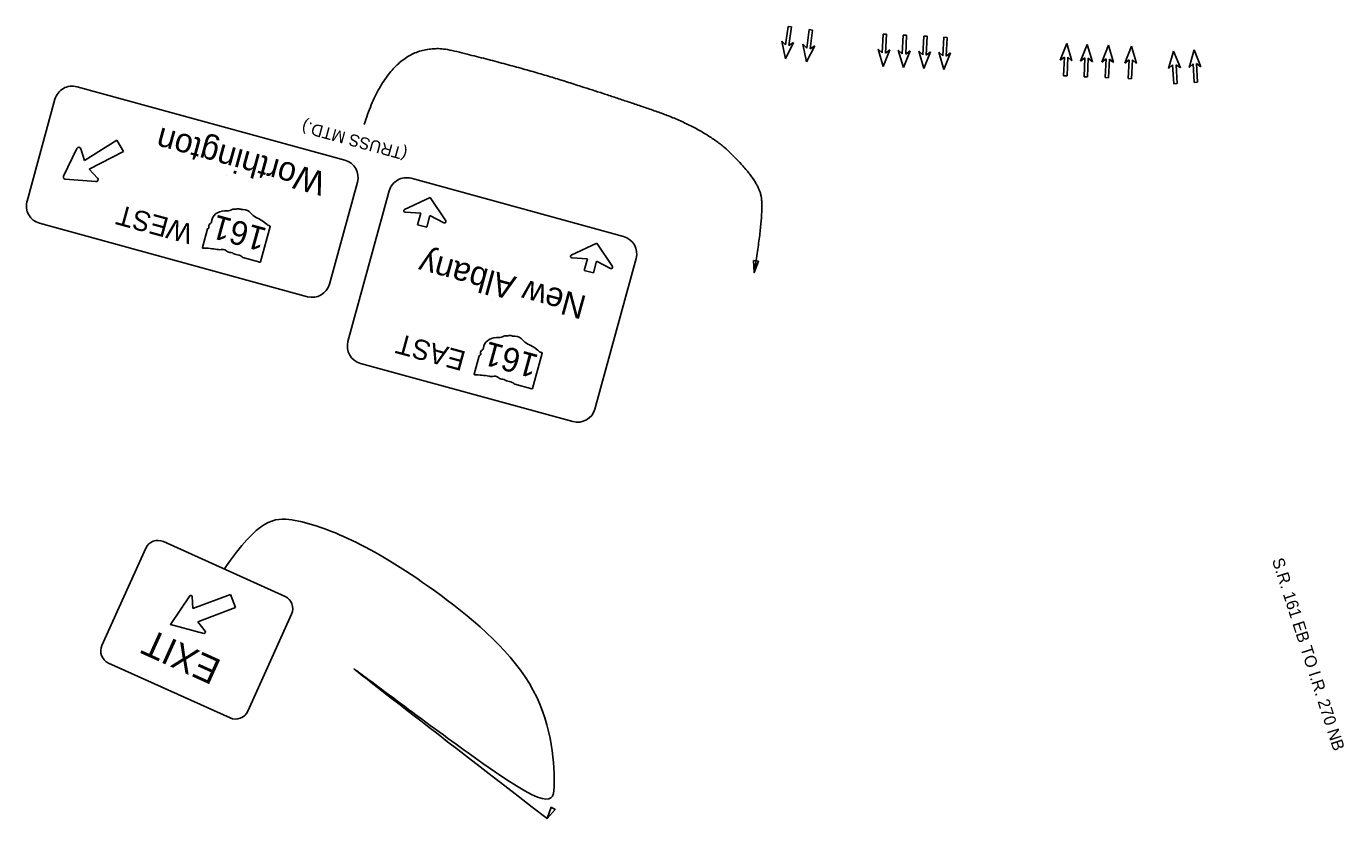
# Model space of a CAD drawing. Extents: x 217413 to 218294, y 612415 to 614235.
# Drawn here: x 217522 to 218294, y 613771 to 614235 of the extents above; entities that cross this region are included whole.
import ezdxf

# ---------------------------------------------------------------- set-up
doc = ezdxf.new("R2010")
doc.units = 0
for name, color, linetype in [('MT_P_Cells', 7, 'Continuous'), ('SH_Text', 7, 'Continuous'), ('SN_P_Text', 7, 'Continuous'), ('SN_X_Public', 7, 'Continuous')]:
    doc.layers.add(name, color=color, linetype=linetype)

msp = doc.modelspace()

# ---------------------------------------------------------------- linework, layer by layer
at = {"layer": 'MT_P_Cells'}
for p, q in [((217966.86, 614223.97), (217968.31, 614234.88)), ((217968.31, 614234.88), (217970.29, 614234.61)), ((217970.29, 614234.61), (217968.84, 614223.71)), ((217969.3, 614234.74), (217969.3, 614234.74)), ((217979.21, 614222.06), (217980.66, 614232.97)), ((217980.66, 614232.97), (217982.64, 614232.7)), ((217982.64, 614232.7), (217981.2, 614221.8)), ((217981.65, 614232.84), (217981.65, 614232.84)), ((218023.39, 614219.35), (218023.93, 614230.34)), ((218023.93, 614230.34), (218025.93, 614230.24)), ((218024.93, 614230.29), (218024.93, 614230.29)), ((218025.93, 614230.24), (218025.38, 614219.25)), ((218035.24, 614218.76), (218035.79, 614229.74)), ((218035.79, 614229.74), (218037.78, 614229.64)), ((218036.78, 614229.69), (218036.78, 614229.69)), ((218037.78, 614229.64), (218037.24, 614218.66)), ((218047.27, 614218.15), (218047.81, 614229.13)), ((218047.81, 614229.13), (218049.81, 614229.04)), ((218048.81, 614229.08), (218048.81, 614229.08)), ((218049.81, 614229.04), (218049.27, 614218.05)), ((218058.95, 614217.55), (218059.49, 614228.54)), ((218059.49, 614228.54), (218061.49, 614228.44)), ((218060.49, 614228.49), (218060.49, 614228.49)), ((218061.49, 614228.44), (218060.95, 614217.46)), ((217966.8, 614215.91), (217964.67, 614226.28)), ((217964.67, 614226.28), (217966.86, 614223.97)), ((217971.56, 614225.37), (217966.8, 614215.91)), ((217968.84, 614223.71), (217971.56, 614225.37)), ((217979.15, 614214), (217977.03, 614224.37)), ((217977.03, 614224.37), (217979.21, 614222.06)), ((217983.91, 614223.46), (217979.15, 614214)), ((217981.2, 614221.8), (217983.91, 614223.46)), ((218023.99, 614211.31), (218021.02, 614221.47)), ((218021.02, 614221.47), (218023.39, 614219.35)), ((218027.95, 614221.13), (218023.99, 614211.31)), ((218025.38, 614219.25), (218027.95, 614221.13)), ((218035.85, 614210.72), (218032.87, 614220.87)), ((218032.87, 614220.87), (218035.24, 614218.76)), ((218039.81, 614220.53), (218035.85, 614210.72)), ((218037.24, 614218.66), (218039.81, 614220.53)), ((218047.87, 614210.11), (218044.9, 614220.27)), ((218044.9, 614220.27), (218047.27, 614218.15)), ((218051.83, 614219.92), (218047.87, 614210.11)), ((218049.27, 614218.05), (218051.83, 614219.92)), ((218059.55, 614209.52), (218056.58, 614219.67)), ((218056.58, 614219.67), (218058.95, 614217.55)), ((218063.51, 614219.33), (218059.55, 614209.52)), ((218060.95, 614217.46), (218063.51, 614219.33)), ((218127.64, 614215.02), (218131.55, 614224.86)), ((218131.55, 614224.86), (218131.55, 614224.86)), ((218131.55, 614224.86), (218134.58, 614214.71)), ((218139.61, 614214.47), (218143.53, 614224.31)), ((218143.53, 614224.31), (218143.53, 614224.31)), ((218143.53, 614224.31), (218146.55, 614214.17)), ((218152.02, 614213.93), (218155.93, 614223.77)), ((218155.93, 614223.77), (218155.93, 614223.77)), ((218155.93, 614223.77), (218158.95, 614213.62)), ((218165.5, 614213.37), (218169.41, 614223.2)), ((218169.41, 614223.2), (218169.41, 614223.2)), ((218169.41, 614223.2), (218172.43, 614213.06)), ((218191.23, 614210.12), (218194.12, 614220.31)), ((218194.12, 614220.31), (218194.12, 614220.31)), ((218194.12, 614220.31), (218198.16, 614210.52)), ((218203.24, 614210.85), (218206.13, 614221.03)), ((218206.13, 614221.03), (218206.13, 614221.03)), ((218206.13, 614221.03), (218210.17, 614211.25)), ((217966.8, 614215.91), (217966.8, 614215.91)), ((217979.15, 614214), (217979.15, 614214)), ((218023.99, 614211.31), (218023.99, 614211.31)), ((218130.2, 614216.91), (218127.64, 614215.02)), ((218129.71, 614205.92), (218130.2, 614216.91)), ((218132.2, 614216.82), (218131.71, 614205.83)), ((218134.58, 614214.71), (218132.2, 614216.82)), ((218142.17, 614216.36), (218139.61, 614214.47)), ((218141.68, 614205.37), (218142.17, 614216.36)), ((218144.17, 614216.27), (218143.68, 614205.28)), ((218146.55, 614214.17), (218144.17, 614216.27)), ((218154.57, 614215.82), (218152.02, 614213.93)), ((218154.09, 614204.83), (218154.57, 614215.82)), ((218156.57, 614215.73), (218156.08, 614204.74)), ((218158.95, 614213.62), (218156.57, 614215.73)), ((218168.06, 614215.26), (218165.5, 614213.37)), ((218167.57, 614204.27), (218168.06, 614215.26)), ((218170.05, 614215.17), (218169.57, 614204.18)), ((218172.43, 614213.06), (218170.05, 614215.17)), ((218193.58, 614212.26), (218191.23, 614210.12)), ((218194.22, 614201.28), (218193.58, 614212.26)), ((218198.16, 614210.52), (218195.58, 614212.38)), ((218195.58, 614212.38), (218196.22, 614201.4)), ((218205.59, 614212.99), (218203.24, 614210.85)), ((218206.23, 614202.01), (218205.59, 614212.99)), ((218210.17, 614211.25), (218207.59, 614213.1)), ((218207.59, 614213.1), (218208.22, 614202.12)), ((218035.85, 614210.72), (218035.85, 614210.72)), ((218047.87, 614210.11), (218047.87, 614210.11)), ((218059.55, 614209.52), (218059.55, 614209.52)), ((218131.71, 614205.83), (218129.71, 614205.92)), ((218130.71, 614205.88), (218130.71, 614205.88)), ((218143.68, 614205.28), (218141.68, 614205.37)), ((218142.68, 614205.33), (218142.68, 614205.33)), ((218156.08, 614204.74), (218154.09, 614204.83)), ((218155.08, 614204.78), (218155.08, 614204.78)), ((218169.57, 614204.18), (218167.57, 614204.27)), ((218168.57, 614204.22), (218168.57, 614204.22)), ((218196.22, 614201.4), (218194.22, 614201.28)), ((218195.22, 614201.34), (218195.22, 614201.34)), ((218208.22, 614202.12), (218206.23, 614202.01)), ((218207.23, 614202.06), (218207.23, 614202.06))]:
    msp.add_line(p, q, dxfattribs=at)
at = {"layer": 'SH_Text'}
for points in [[(217948.15, 614097.71), (217950.91, 614097.25), (217948.38, 614090.57)], [(217829.48, 613777.32), (217831.89, 613775.91), (217827.15, 613770.57)]]:
    msp.add_lwpolyline(points, close=True, dxfattribs=at)
for points, degree in [([(217948.38, 614090.57), (217954.64, 614127.11), (217950.04, 614145.51), (217919.75, 614175.19), (217860.42, 614195.59), (217808.4, 614211.75), (217736.45, 614229.27), (217719.98, 614177.39)], 2), ([(217638.02, 613916.85), (217658.24, 613946.4), (217676.59, 613947.98), (217710.8, 613936.14), (217757.4, 613909.03), (217827.54, 613851.77), (217833.39, 613781.96), (217827.15, 613770.57), (217638.02, 613916.85), (217827.15, 613770.57)], 3)]:
    msp.add_open_spline(points, degree=degree, dxfattribs=at)
at = {"layer": 'SN_X_Public'}
for p, q in [((217551.79, 614199.49), (217708.66, 614156.49)), ((217522.47, 614132.42), (217538.83, 614192.11)), ((217556.1, 614156.23), (217575.19, 614168.19)), ((217575.19, 614168.19), (217578.95, 614161.58)), ((217543.87, 614147.12), (217551.72, 614163.34)), ((217554.02, 614163.16), (217556.1, 614156.23)), ((217578.95, 614161.58), (217558.93, 614151.26)), ((217558.93, 614151.26), (217563.83, 614145.94)), ((217562.82, 614143.87), (217544.86, 614145.38)), ((217639.43, 614147.74), (217639.43, 614147.74)), ((217716.05, 614143.53), (217699.68, 614083.84)), ((217747.61, 614145.82), (217871.93, 614111.74)), ((217758.57, 614134.66), (217743.63, 614127.46)), ((217767.74, 614120.85), (217758.57, 614134.66)), ((217686.72, 614076.46), (217529.85, 614119.46)), ((217744.03, 614125.95), (217753.16, 614125.47)), ((217753.16, 614125.47), (217751.28, 614118.59)), ((217751.28, 614118.59), (217756.64, 614117.12)), ((217756.64, 614117.12), (217758.53, 614124)), ((217758.53, 614124), (217766.63, 614119.76)), ((217625.19, 614105.35), (217628.15, 614116.12)), ((217664.98, 614117.51), (217659.34, 614096.92)), ((217856.21, 614107.89), (217841.28, 614100.69)), ((217865.39, 614094.08), (217856.21, 614107.89)), ((217658.9, 614096.66), (217648.98, 614099.38)), ((217841.68, 614099.18), (217850.81, 614098.7)), ((217850.81, 614098.7), (217848.93, 614091.83)), ((217854.29, 614090.36), (217856.18, 614097.23)), ((217856.18, 614097.23), (217864.28, 614092.99)), ((217848.93, 614091.83), (217854.29, 614090.36)), ((217794.9, 614074.53), (217794.9, 614074.53)), ((217784.42, 614031.11), (217787.37, 614041.88)), ((217824.2, 614043.26), (217818.56, 614022.68)), ((217842.19, 614003.24), (217717.87, 614037.32)), ((217818.13, 614022.41), (217808.2, 614025.14)), ((217619.19, 613900.66), (217619.2, 613900.66)), ((217619.2, 613900.66), (217619.61, 613893.69)), ((217619.61, 613893.69), (217641.66, 613902.01)), ((217641.66, 613902.01), (217644.6, 613894.21)), ((217644.6, 613894.21), (217622.56, 613885.89)), ((217626.03, 613879.14), (217606.47, 613884.28)), ((217622.56, 613885.89), (217626.84, 613880.38))]:
    msp.add_line(p, q, dxfattribs=at)
for points in [[(217710.49, 614050.28), (217734.65, 614138.43)], [(217879.31, 614098.78), (217855.15, 614010.62)], [(217566.34, 613872.09), (217592.09, 613929.04)], [(217602.42, 613932.94), (217673.61, 613900.75)], [(217606.47, 613884.28), (217606.47, 613884.28), (217617.76, 613901.05)], [(217677.51, 613890.42), (217651.76, 613833.47)], [(217641.42, 613829.57), (217570.24, 613861.75)]]:
    msp.add_lwpolyline(points, dxfattribs=at)
for centre, radius, start, end in [((217549.01, 614189.32), 10.55, 74.6708, 164.6708), ((217552.83, 614162.8), 1.24, 16.69459, 154.16791), ((217705.87, 614146.32), 10.55, 344.6708, 74.6708), ((217545, 614146.61), 1.24, 155.57716, 263.76444), ((217562.92, 614145.1), 1.24, 265.17369, 42.64701), ((217744.82, 614135.64), 10.55, 74.6708, 164.6708), ((217532.64, 614129.63), 10.55, 164.6708, 254.6708), ((217869.14, 614101.57), 10.55, 344.6708, 74.6708), ((217689.51, 614086.63), 10.55, 254.6708, 344.6708), ((217720.66, 614047.49), 10.55, 164.6708, 254.6708), ((217844.98, 614013.41), 10.55, 254.6708, 344.6708), ((217599.2, 613925.82), 7.81, 65.67027, 155.67027), ((217618.41, 613900.62), 0.781, 3.48975, 146.06263), ((217670.39, 613893.63), 7.81, 335.67027, 65.67027), ((217626.22, 613879.91), 0.781, 255.27791, 37.85079), ((217573.45, 613868.87), 7.81, 155.67027, 245.67027), ((217644.64, 613836.68), 7.81, 245.67027, 335.67027)]:
    msp.add_arc(centre, radius, start, end, dxfattribs=at)
for centre, major_axis, ratio, start_param, end_param in [((217639.82, 614119.24), (-8.99, 2.47), 0.8, 5.101752, 6.440018), ((217638.93, 614130.86), (-4.93, 1.35), 0.8, 1.647645, 2.488434), ((217644.13, 614125.37), (-2.91, 0.8), 0.8, 4.937069, 5.64225), ((217644.58, 614128.29), (-0.773, 0.212), 0.8, 1.147584, 2.315152), ((217646.52, 614125.62), (-2.75, 0.75), 0.8, 4.691044, 5.507374), ((217648.42, 614131.09), (-4.24, 1.16), 0.8, 1.495662, 1.94098), ((217649.45, 614123.15), (-5.16, 1.41), 0.8, 4.026481, 4.996735), ((217744.04, 614126.75), (0.825, -0.226), 0.925816, 2.325901, 4.943538), ((217632.54, 614117.23), (-3.51, 0.96), 0.8, 5.934695, 6.695948), ((217628.03, 614121), (-2.55, 0.7), 0.8, 2.387724, 3.262537), ((217660.42, 614128.7), (-8.12, 2.23), 0.8, 0.823519, 1.323587), ((217645.4, 614104.27), (-25.97, 7.12), 0.8, 4.195997, 4.488961), ((217664.23, 614118.99), (-1.09, 0.3), 0.8, 0.519207, 1.627899), ((217767.03, 614120.45), (-0.825, 0.226), 0.925815, 1.339647, 3.957285), ((217628.56, 614116.05), (-0.404, 0.111), 0.8, 5.05454, 6.418171), ((217628.45, 614116.89), (-0.584, 0.16), 0.8, 1.883978, 3.671073), ((217663.96, 614115.57), (-3.02, 0.83), 0.8, 4.665946, 4.897461), ((217664.6, 614117.66), (-0.396, 0.109), 0.8, 3.00124, 4.508301), ((217625.56, 614105.21), (-0.377, 0.103), 0.8, 6.141152, 7.989035), ((217629.72, 614074.49), (-35.96, 9.86), 0.8, 4.814394, 5.042369), ((217634.55, 614110.1), (-7.23, 1.98), 0.8, 1.699011, 2.107814), ((217637.49, 614101.8), (-2.75, 0.75), 0.8, 4.081561, 5.145723), ((217641.34, 614104.25), (-2.29, 0.63), 0.8, 0.950623, 2.079405), ((217642.3, 614101.43), (-1.1, 0.3), 0.8, 3.836095, 5.185415), ((217648.52, 614111.93), (-13.68, 3.75), 0.8, 1.404758, 1.657858), ((217645.96, 614097.64), (-3.81, 1.04), 0.8, 4.042523, 4.731795), ((217658.94, 614096.99), (-0.393, 0.108), 0.8, 1.712693, 3.28349), ((217841.69, 614099.98), (0.825, -0.226), 0.925816, 2.325901, 4.943538), ((217864.67, 614093.68), (-0.825, 0.226), 0.925815, 1.339647, 3.957285), ((217799.04, 614044.99), (-8.99, 2.47), 0.8, 5.101752, 6.440018), ((217798.15, 614056.62), (-4.93, 1.35), 0.8, 1.647645, 2.488434), ((217803.35, 614051.12), (-2.91, 0.8), 0.8, 4.937069, 5.64225), ((217803.8, 614054.04), (-0.773, 0.212), 0.8, 1.147584, 2.315152), ((217805.74, 614051.37), (-2.75, 0.75), 0.8, 4.691044, 5.507374), ((217807.64, 614056.84), (-4.24, 1.16), 0.8, 1.495662, 1.94098), ((217808.67, 614048.91), (-5.16, 1.41), 0.8, 4.026481, 4.996735), ((217819.64, 614054.46), (-8.12, 2.23), 0.8, 0.823519, 1.323587), ((217787.78, 614041.81), (-0.404, 0.111), 0.8, 5.05454, 6.418171), ((217787.67, 614042.64), (-0.584, 0.16), 0.8, 1.883978, 3.671073), ((217791.76, 614042.99), (-3.51, 0.96), 0.8, 5.934695, 6.695948), ((217787.25, 614046.75), (-2.55, 0.7), 0.8, 2.387724, 3.262537), ((217804.62, 614030.02), (-25.97, 7.12), 0.8, 4.195997, 4.488961), ((217823.46, 614044.75), (-1.09, 0.3), 0.8, 0.519207, 1.627899), ((217823.18, 614041.33), (-3.02, 0.83), 0.8, 4.665946, 4.897461), ((217823.82, 614043.42), (-0.396, 0.109), 0.8, 3.00124, 4.508301), ((217784.78, 614030.96), (-0.377, 0.103), 0.8, 6.141152, 7.989035), ((217788.94, 614000.24), (-35.96, 9.86), 0.8, 4.814394, 5.042369), ((217793.77, 614035.85), (-7.23, 1.98), 0.8, 1.699011, 2.107814), ((217796.72, 614027.55), (-2.75, 0.75), 0.8, 4.081561, 5.145723), ((217800.56, 614030.01), (-2.29, 0.63), 0.8, 0.950623, 2.079405), ((217801.52, 614027.19), (-1.1, 0.3), 0.8, 3.836095, 5.185415), ((217807.74, 614037.69), (-13.68, 3.75), 0.8, 1.404758, 1.657858), ((217805.18, 614023.39), (-3.81, 1.04), 0.8, 4.042523, 4.731795), ((217818.16, 614022.74), (-0.393, 0.108), 0.8, 1.712693, 3.28349)]:
    msp.add_ellipse(centre, major_axis=major_axis, ratio=ratio, start_param=start_param, end_param=end_param, dxfattribs=at)

# ---------------------------------------------------------------- texts
at = {"layer": 'SH_Text'}
msp.add_text('S.R. 161 EB TO I.R. 270 NB', height=7, rotation=287.87494, dxfattribs=at).set_placement((218251.7, 613922.07))
at = {"layer": 'SN_P_Text'}
msp.add_text('(TRUSS MTD.)', height=7, rotation=164.6708, dxfattribs=at).set_placement((217745.75, 614162.92))
at = {"layer": 'SN_X_Public'}
for s, height, rotation, p in [('Worthington', 14.0625, 164.6708, (217698.38, 614149)), ('WEST', 11.719, 164.6708, (217620.57, 614118.44)), ('161', 14.063, 164.6708, (217663.66, 614116.31)), ('New Albany', 14.062, 164.6708, (217851, 614076.56)), ('EAST', 11.719, 164.6708, (217780.24, 614044.07)), ('161', 14.063, 164.6708, (217822.88, 614042.06)), ('EXIT', 15.625, 155.67027, (217637.14, 613862.94))]:
    msp.add_text(s, height=height, rotation=rotation, dxfattribs=at).set_placement(p)

doc.saveas('drawing.dxf')
